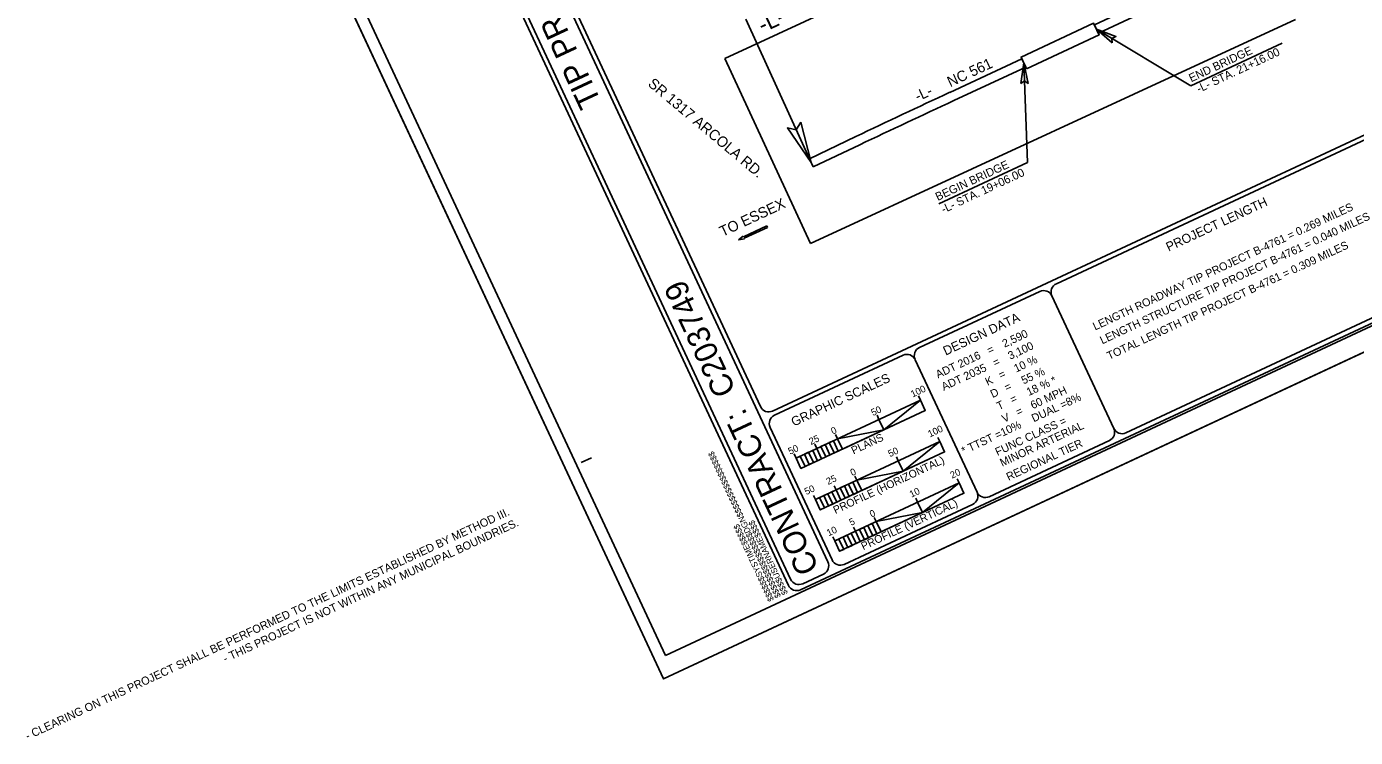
# Model space of a CAD drawing. Extents: x 2318983 to 2324558, y 920396 to 924651.
# Drawn here: x 2318983 to 2322471, y 920396 to 922262 of the extents above; entities that cross this region are included whole.
import ezdxf

# ---------------------------------------------------------------- set-up
doc = ezdxf.new("R2010")
doc.units = 0
for name, color, linetype in [('Old_Level_1', 7, 'Continuous'), ('Prop Dimension', 7, 'Continuous'), ('Prop DSN Text', 7, 'Continuous'), ('Prop Shade Light', 7, 'Continuous'), ('Prop Shade Medium', 7, 'Continuous'), ('Prop Terminator CELL', 7, 'Continuous'), ('Sheet Cutting Line CELL', 7, 'Continuous'), ('Sheet Data Field CELL', 7, 'Continuous'), ('Sheet Plot Border Inside CELL', 7, 'Continuous'), ('Sheet Plot Border Outside CELL', 7, 'Continuous'), ('Sheet Title CELL', 7, 'Continuous')]:
    doc.layers.add(name, color=color, linetype=linetype)

msp = doc.modelspace()

# ---------------------------------------------------------------- linework, layer by layer
at = {"layer": 'Old_Level_1'}
for p, q in [((2321790.6, 922255.3), (2322038.3, 922106.4)), ((2322038.3, 922106.4), (2322278.7, 922218.6)), ((2321600.3, 922166.5), (2321610.2, 921904.9)), ((2321377.6, 921796.4), (2321610.2, 921904.9))]:
    msp.add_line(p, q, dxfattribs=at)
at = {"layer": 'Prop Dimension'}
for p, q in [((2320815.9, 922178.3), (2322085.9, 922766.6)), ((2322313.3, 922280), (2321040.8, 921692.7)), ((2321040.8, 921692.7), (2320815.9, 922178.3))]:
    msp.add_line(p, q, dxfattribs=at)
at = {"layer": 'Prop DSN Text'}
for p, q in [((2320871.1, 922281.4), (2321042.6, 921904.9)), ((2320864.8, 921710.1), (2320925.7, 921738.5)), ((2320927.3, 921734.9), (2320866.4, 921706.5)), ((2320925.7, 921738.5), (2320927.3, 921734.9)), ((2320851.9, 921701.9), (2320864, 921711.7)), ((2320867.2, 921704.9), (2320851.9, 921701.9)), ((2320864, 921711.7), (2320864.8, 921710.1)), ((2320866.4, 921706.5), (2320867.2, 921704.9))]:
    msp.add_line(p, q, dxfattribs=at)
at = {"layer": 'Prop Shade Light'}
for p, q in [((2321595.2, 922177.4), (2321406.1, 922089.2)), ((2321605.4, 922155.7), (2321595.2, 922177.4)), ((2321416.2, 922067.5), (2321605.4, 922155.7)), ((2321159.4, 921973.4), (2321037.9, 921914.8)), ((2321047.7, 921894.1), (2321169.7, 921951.7)), ((2321037.9, 921914.8), (2321047.7, 921894.1))]:
    msp.add_line(p, q, dxfattribs=at)
msp.add_lwpolyline([(2321795.7, 922244.4), (2321785.6, 922266.1), (2321799.3, 922272.5), (2322514, 922606.4), (2322532.6, 922566.6), (2322520.8, 922563.9), (2322506.2, 922560.4), (2322484.7, 922554.6), (2322461.3, 922548), (2322451.7, 922545.1), (2322448.3, 922544.1), (2322446, 922543.4), (2322439.7, 922541.4), (2322439.7, 922541.4), (2322439.7, 922541.4), (2322392.8, 922523.2), (2321809.5, 922250.8)], close=True, dxfattribs=at)
for radius in [50012, 49988]:
    msp.add_arc((2342535.2, 876759.8), radius, 114.9913, 115.30347, dxfattribs=at)
at = {"layer": 'Prop Shade Medium'}
msp.add_line((2321047.7, 921894.1), (2321037.9, 921914.8), dxfattribs=at)
msp.add_lwpolyline([(2321607.5, 922151.1), (2321593.1, 922181.9), (2321783.4, 922270.7), (2321797.8, 922239.8)], close=True, dxfattribs=at)
at = {"layer": 'Prop Terminator CELL'}
for points in [[(2321832, 922219.3), (2321790.6, 922255.3), (2321842.1, 922235.4), (2321831.2, 922230.7)], [(2321592.8, 922112.3), (2321600.3, 922166.5), (2321611.7, 922112.6), (2321601.8, 922119.2)], [(2321014.7, 922010.9), (2321042.6, 921904.9), (2320980.1, 921995.8), (2321003.3, 921991.2)]]:
    msp.add_lwpolyline(points, close=True, dxfattribs=at)
at = {"layer": 'Sheet Cutting Line CELL'}
for p, q in [((2319538.3, 922942), (2320654.8, 920549.7)), ((2320654.8, 920549.7), (2324317.2, 922258.9))]:
    msp.add_line(p, q, dxfattribs=at)
at = {"layer": 'Sheet Data Field CELL'}
for p, q in [((2321328.9, 921281.7), (2321323.8, 921292.6)), ((2321220.1, 921231), (2321215.1, 921241.8)), ((2321057.1, 921154.8), (2321052, 921165.7)), ((2321002.7, 921129.5), (2320997.6, 921140.3)), ((2320992.6, 920773.6), (2320992.6, 920773.6))]:
    msp.add_line(p, q, dxfattribs=at)
at = {"layer": 'Sheet Plot Border Inside CELL'}
msp.add_lwpolyline([(2320660.3, 920611.7), (2324284.6, 922303.2), (2323213.7, 924597.8), (2319589.4, 922906.3)], close=True, dxfattribs=at)
at = {"layer": 'Sheet Plot Border Outside CELL'}
msp.add_lwpolyline([(2323200.7, 924651.2), (2319538.3, 922942), (2320654.8, 920549.7), (2324317.2, 922258.9)], close=True, dxfattribs=at)
at = {"layer": 'Sheet Title CELL'}
for p, q in [((2320909.2, 921264.4), (2320061.7, 923080.3)), ((2321086.1, 920856.9), (2320050.8, 923075.2)), ((2320941.1, 921252.8), (2324029.4, 922694)), ((2321685.7, 921587), (2322512.1, 921972.7)), ((2321326.8, 921419.5), (2321642.1, 921566.7)), ((2321674, 921555.1), (2321836.4, 921207.1)), ((2320946.2, 921241.9), (2321283.3, 921399.2)), ((2321315.2, 921387.6), (2321477.6, 921039.6)), ((2321328.9, 921281.7), (2321002.7, 921129.4)), ((2321328.9, 921281.7), (2321323.8, 921292.6)), ((2321341.6, 921254.5), (2321328.9, 921281.7)), ((2321015.3, 921102.3), (2321341.6, 921254.5)), ((2321220.1, 921230.9), (2321215.1, 921241.8)), ((2321220.1, 921230.9), (2321232.8, 921203.8)), ((2321097, 920862), (2320934.6, 921210)), ((2321057, 921154.8), (2321051.9, 921165.7)), ((2321379.6, 921173), (2321053.4, 921020.7)), ((2321379.6, 921173), (2321053.4, 921020.7)), ((2321078.8, 921165), (2321091.5, 921137.8)), ((2321111.4, 921180.2), (2321106.3, 921191)), ((2321379.6, 921173), (2321374.6, 921183.8)), ((2321379.6, 921173), (2321374.6, 921183.8)), ((2321392.3, 921145.8), (2321379.6, 921173)), ((2320438.8, 921117.6), (2320465.9, 921130.3)), ((2320438.8, 921117.6), (2320465.9, 921130.3)), ((2321002.7, 921129.4), (2320997.6, 921140.3)), ((2320997.6, 921140.3), (2320997.6, 921140.3)), ((2321002.7, 921129.4), (2321015.3, 921102.3)), ((2321002.7, 921129.4), (2321002.7, 921129.4)), ((2321066.1, 920993.5), (2321392.3, 921145.8)), ((2321270.9, 921122.2), (2321265.8, 921133.1)), ((2321270.9, 921122.2), (2321265.8, 921133.1)), ((2321270.9, 921122.2), (2321283.6, 921095)), ((2321107.8, 921046.1), (2321102.7, 921057)), ((2321107.8, 921046.1), (2321102.7, 921057)), ((2321430.4, 921064.2), (2321104.2, 920911.9)), ((2321430.4, 921064.2), (2321104.2, 920911.9)), ((2321430.4, 921064.2), (2321104.2, 920911.9)), ((2321129.5, 921056.2), (2321142.2, 921029)), ((2321162.1, 921071.5), (2321157.1, 921082.3)), ((2321162.1, 921071.5), (2321157.1, 921082.3)), ((2321430.4, 921064.2), (2321425.3, 921075.1)), ((2321430.4, 921064.2), (2321425.3, 921075.1)), ((2321430.4, 921064.2), (2321425.3, 921075.1)), ((2321443.1, 921037), (2321430.4, 921064.2)), ((2321053.4, 921020.7), (2321048.3, 921031.6)), ((2321053.4, 921020.7), (2321048.3, 921031.6)), ((2321048.3, 921031.6), (2321048.3, 921031.6)), ((2321053.4, 921020.7), (2321066.1, 920993.5)), ((2321053.4, 921020.7), (2321053.4, 921020.7)), ((2321053.4, 921020.7), (2321053.4, 921020.7)), ((2321116.8, 920884.8), (2321443.1, 921037)), ((2321321.6, 921013.4), (2321316.6, 921024.3)), ((2321321.6, 921013.4), (2321316.6, 921024.3)), ((2321321.6, 921013.4), (2321316.6, 921024.3)), ((2321321.6, 921013.4), (2321334.3, 920986.3)), ((2321212.9, 920962.7), (2321207.9, 920973.6)), ((2321212.9, 920962.7), (2321207.9, 920973.6)), ((2321212.9, 920962.7), (2321207.9, 920973.6)), ((2321104.2, 920911.9), (2321099.1, 920922.8)), ((2321104.2, 920911.9), (2321099.1, 920922.8)), ((2321104.2, 920911.9), (2321099.1, 920922.8)), ((2321099.1, 920922.8), (2321099.1, 920922.8)), ((2321158.5, 920937.3), (2321153.5, 920948.2)), ((2321158.5, 920937.3), (2321153.5, 920948.2)), ((2321158.5, 920937.3), (2321153.5, 920948.2)), ((2321180.3, 920947.5), (2321193, 920920.3)), ((2321104.2, 920911.9), (2321116.8, 920884.8)), ((2321104.2, 920911.9), (2321104.2, 920911.9)), ((2321104.2, 920911.9), (2321104.2, 920911.9)), ((2321104.2, 920911.9), (2321104.2, 920911.9)), ((2320992.6, 920773.6), (2320992.6, 920773.6)), ((2320992.6, 920773.6), (2320992.6, 920773.6)), ((2320992.6, 920773.6), (2320992.6, 920773.6)), ((2320992.6, 920773.6), (2320992.6, 920773.6))]:
    msp.add_line(p, q, dxfattribs=at)
for points in [[(2319937, 923035.4), (2320982.5, 920795.3)], [(2319937, 923035.4), (2320982.5, 920795.3)], [(2319953, 923029.6), (2320988.3, 920811.3)], [(2321014.4, 920783.7), (2324233.1, 922285.9)], [(2321868.4, 921195.5), (2322694.8, 921581.2)], [(2321509.5, 921028), (2321824.8, 921175.2)], [(2321128.9, 920850.4), (2321466, 921007.7)], [(2321020.1, 920799.7), (2321074.5, 920825)]]:
    msp.add_lwpolyline(points, dxfattribs=at)
for points in [[(2321328.9, 921281.7), (2321232.8, 921203.8), (2321341.6, 921254.5)], [(2321111.4, 921180.2), (2321232.8, 921203.8), (2321124.1, 921153)], [(2321067.9, 921159.9), (2321078.8, 921165), (2321091.5, 921137.8), (2321080.6, 921132.7)], [(2321089.6, 921170), (2321100.5, 921175.1), (2321113.2, 921147.9), (2321102.3, 921142.9)], [(2321379.6, 921173), (2321283.6, 921095), (2321392.3, 921145.8)], [(2321002.7, 921129.4), (2321013.5, 921134.5), (2321026.2, 921107.3), (2321015.3, 921102.3)], [(2321024.4, 921139.6), (2321035.3, 921144.6), (2321048, 921117.5), (2321037.1, 921112.4)], [(2321046.2, 921149.7), (2321057, 921154.8), (2321069.7, 921127.6), (2321058.8, 921122.6)], [(2321162.1, 921071.5), (2321283.6, 921095), (2321174.8, 921044.2)], [(2321118.7, 921051.1), (2321129.5, 921056.2), (2321142.2, 921029), (2321131.3, 921024)], [(2321140.4, 921061.3), (2321151.3, 921066.4), (2321164, 921039.2), (2321153.1, 921034.1)], [(2321430.4, 921064.2), (2321334.3, 920986.3), (2321443.1, 921037)], [(2321053.4, 921020.7), (2321064.3, 921025.8), (2321077, 920998.6), (2321066.1, 920993.5)], [(2321075.2, 921030.9), (2321086, 921035.9), (2321098.8, 921008.7), (2321087.8, 921003.7)], [(2321096.9, 921041), (2321107.8, 921046.1), (2321120.5, 921018.9), (2321109.6, 921013.8)], [(2321212.9, 920962.7), (2321334.3, 920986.3), (2321225.6, 920935.5)], [(2321191.2, 920952.5), (2321202, 920957.6), (2321214.7, 920930.5), (2321203.8, 920925.4)], [(2321104.2, 920911.9), (2321115, 920917), (2321127.7, 920889.8), (2321116.8, 920884.8)], [(2321125.9, 920922.1), (2321136.8, 920927.2), (2321149.5, 920900), (2321138.6, 920894.9)], [(2321147.6, 920932.3), (2321158.5, 920937.3), (2321171.2, 920910.1), (2321160.3, 920905.1)], [(2321169.4, 920942.4), (2321180.3, 920947.5), (2321193, 920920.3), (2321182.1, 920915.2)]]:
    msp.add_lwpolyline(points, close=True, dxfattribs=at)
for centre, start, end in [((2321695.8, 921565.3), 115.0187, 205.0187), ((2321652.3, 921545), 25.0187, 115.0187), ((2321336.9, 921397.9), 115.0187, 205.0187), ((2321293.4, 921377.6), 25.0187, 115.0187), ((2320930.9, 921274.6), 205.0187, 295.0187), ((2320956.3, 921220.2), 115.0187, 205.0187), ((2321814.7, 921197.1), 295.0187, 25.0187), ((2321858.2, 921217.4), 205.0187, 295.0187), ((2321455.8, 921029.6), 295.0187, 25.0187), ((2321499.3, 921049.9), 205.0187, 295.0187), ((2321064.3, 920846.9), 295.0187, 25.0187), ((2321118.7, 920872.3), 205.0187, 295.0187), ((2321010, 920821.5), 205.0187, 295.0187), ((2321004.2, 920805.6), 205.0187, 295.0187)]:
    msp.add_arc(centre, 24, start, end, dxfattribs=at)

# ---------------------------------------------------------------- texts
at = {"layer": 'Old_Level_1'}
for s, height, rotation, p in [('END BRIDGE', 21.6, 25.0187, (2322039.6, 922115.5)), ('NC 561', 27.68, 24.9912, (2321407.2, 922102.5)), ('-L- STA. 21+16.00 ', 21.6, 25.0187, (2322059.8, 922087.6)), ('-L-', 27.68, 24.9912, (2321322, 922064.8)), ('BEGIN BRIDGE', 21.6, 25.0187, (2321374.4, 921804.1)), ('-L- STA. 19+06.00 ', 21.6, 25.0187, (2321389.7, 921771.3)), ('- CLEARING ON THIS PROJECT SHALL BE PERFORMED TO THE LIMITS ESTABLISHED BY METHOD III.', 21.357, 25.0187, (2318986.1, 920389.4)), ('- THIS PROJECT IS NOT WITHIN ANY MUNICIPAL BOUNDRIES.', 21.357, 25.0187, (2319504.7, 920592.2))]:
    msp.add_text(s, height=height, rotation=rotation, dxfattribs=at).set_placement(p)
at = {"layer": 'Prop DSN Text'}
for s, height, rotation, p in [('-L- STA. 12+90.00', 43.2, 25.0187, (2320914.9, 922244.4)), ('SR 1317 ARCOLA RD. ', 27.683, 319.9237, (2320611.7, 922108.2)), ('TO ESSEX', 27.68, 25.0187, (2320809.7, 921709.7))]:
    msp.add_text(s, height=height, rotation=rotation, dxfattribs=at).set_placement(p)
at = {"layer": 'Sheet Data Field CELL'}
for s, height, p in [('LENGTH ROADWAY TIP PROJECT B-4761 = 0.269 MILES ', 21, (2321787.4, 921464.1)), ('LENGTH STRUCTURE TIP PROJECT B-4761 = 0.040 MILES ', 21, (2321806.1, 921427.7)), ('TOTAL LENGTH TIP PROJECT B-4761 = 0.309 MILES', 21, (2321824.3, 921386.9)), ('2,590', 21, (2321549.7, 921419)), ('ADT 2016', 21, (2321375, 921338.2)), ('=', 21, (2321509.7, 921401.2)), ('3,100', 21, (2321564.6, 921387.2)), ('ADT 2035', 21, (2321390.2, 921305.8)), ('=', 21, (2321524.9, 921368.6)), ('10 %', 21, (2321580.1, 921353.7)), ('K', 21, (2321505, 921319)), ('=', 21, (2321540, 921336.3)), ('55 %', 21, (2321599.7, 921322.5)), ('18 % *', 21, (2321613.2, 921292)), ('100', 18, (2321308.6, 921288.2)), ('D', 21, (2321518.4, 921286.7)), ('=', 21, (2321555.2, 921303.7)), ('60 MPH', 21, (2321623.8, 921257.3)), ('50', 18, (2321204.4, 921239.5)), ('T', 21, (2321534.9, 921255)), ('=', 21, (2321570.1, 921271.9)), ('DUAL =8%  ', 21, (2321626.5, 921223.1)), ('FUNC CLASS =', 21, (2321531.1, 921134.8)), ('V', 21, (2321548.5, 921221.9)), ('=', 21, (2321585.3, 921239.3)), ('100', 18, (2321353.7, 921183.4)), ('* TTST =10%', 21, (2321442.5, 921137.9)), ('MINOR ARTERIAL', 21, (2321543.6, 921106.5)), ('50', 18, (2320986.9, 921138)), ('25', 18, (2321041.6, 921163.5)), ('REGIONAL TIER', 21, (2321560.3, 921069.5)), ('50', 18, (2321249, 921131.5)), ('20', 18, (2321412.1, 921075.1)), ('50', 18, (2321029.5, 921032.1)), ('25', 18, (2321086.7, 921058.7)), ('10', 18, (2321305.3, 921025.3)), ('5', 18, (2321147, 920951.4)), ('10', 18, (2321087.9, 920923.8))]:
    msp.add_text(s, height=height, rotation=25.0187, dxfattribs=at).set_placement(p)
at = {"layer": 'Sheet Title CELL'}
for s, height, rotation, p in [('TIP PROJECT:', 60, 115.0187, (2320492.5, 922064.3)), ('PROJECT LENGTH', 23.999, 25.0187, (2321980.3, 921671.1)), ('C203749', 60, 115.0187, (2320846, 921306.8)), ('DESIGN DATA', 23.999, 25.0187, (2321395.4, 921398.1)), ('GRAPHIC SCALES', 23.999, 25.0187, (2320996.7, 921212)), ('CONTRACT:', 60, 115.0187, (2321063.9, 920839.9)), ('0', 18, 25.0187, (2321099.2, 921190.8)), ('PLANS', 20.4, 25.0187, (2321153.2, 921138.8)), ('$$$$$$$$$$$$$$$$DGN$$$$$$$$$$$$$$$$', 15.75, 115.0187, (2320963.5, 920766.6)), ('PROFILE (HORIZONTAL)', 20.399, 25.0187, (2321105.8, 920982.5)), ('0', 18, 25.0187, (2321149.9, 921082)), ('0', 18, 25.0187, (2321150.1, 921081.7)), ('PROFILE (VERTICAL)', 20.399, 25.0187, (2321179, 920887.5)), ('0', 18, 25.0187, (2321200.7, 920973.3)), ('0', 18, 25.0187, (2321200.8, 920973)), ('0', 18, 25.0187, (2321200.8, 920973)), ('$$$$$$SYSTIME$$$$$', 15.75, 115.0187, (2320945.3, 920757.5)), ('$$$$USERNAME$$$$', 15.75, 115.0187, (2320981.5, 920774.6))]:
    msp.add_text(s, height=height, rotation=rotation, dxfattribs=at).set_placement(p)

doc.saveas('drawing.dxf')
